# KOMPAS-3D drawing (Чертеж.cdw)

Referenced files in C:\Documents and Settings\Вадим\Мои документы\Мои рисунки\: Чертеж.cdw
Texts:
  133 1 134 1 135 1 136 0 50 1|SPDS|133 1 134 1 135 1 136 0 50 1
  125 1 126 1 127 1 128 0 50 1|SPDS|125 1 126 1 127 1 128 0 50 1
  129 1 130 1 131 1 132 0 50 1|SPDS|129 1 130 1 131 1 132 0 50 1
  Слой 1
  План механизма
  План скоростей для двух
  положений механизма
  a BC
  a BD
  a DE
  a n BC
  a n DE
  План ускорений для первого
  положения кривошипа
  План ускорений для второго
Dimensions and other numbers on the sheet: 1; 2; 3; 4; 5; 1:1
